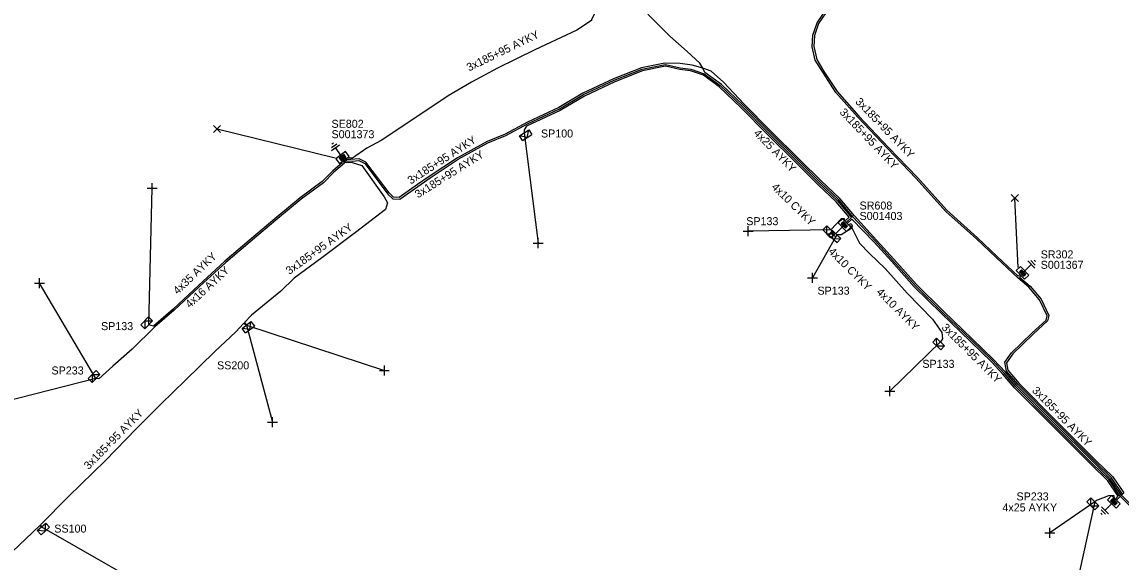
# Model space of a CAD drawing. Extents: x -763093 to -760976, y -1155572 to -1152009.
# Drawn here: x -761822.3 to -761685, y -1155229.2 to -1155161.8 of the extents above; entities that cross this region are included whole.
import ezdxf

# ---------------------------------------------------------------- set-up
doc = ezdxf.new("R2010")
doc.units = 0
for name, color, linetype in [('Vrstva 1', 7, 'Continuous'), ('Vrstva 14', 7, 'Continuous'), ('Vrstva 15', 7, 'Continuous'), ('Vrstva 28', 7, 'Continuous'), ('Vrstva 29', 7, 'Continuous'), ('Vrstva 30', 7, 'Continuous'), ('Vrstva 31', 7, 'Continuous'), ('Vrstva 33', 7, 'Continuous'), ('Vrstva 34', 7, 'Continuous'), ('Vrstva 5', 7, 'Continuous'), ('Vrstva 59', 7, 'Continuous'), ('Vrstva 6', 7, 'Continuous'), ('Vrstva 8', 7, 'Continuous'), ('Vrstva 9', 7, 'Continuous')]:
    doc.layers.add(name, color=color, linetype=linetype)

# ---------------------------------------------------------------- blocks, each defined once
blk = doc.blocks.new('NN800')
at = {"layer": 'Vrstva 1'}
for points in [[(-0.44, 0.44), (0.44, -0.44)], [(-0.44, -0.44), (0.44, 0.44)]]:
    blk.add_lwpolyline(points, dxfattribs=at)
blk = doc.blocks.new('NN620')
at = {"layer": 'Vrstva 8'}
for points in [[(0.75, 0), (-0.75, 0)], [(-0.75, 0), (-0.75, -0.75)], [(0.75, -0.75), (0.75, 0)], [(-0.75, -0.75), (0.75, -0.75)], [(0.37, -0.18), (-0.38, -0.18)], [(-0.38, -0.18), (-0.38, -0.56)], [(-0.38, -0.56), (0.37, -0.56)], [(0.32, -0.23), (-0.33, -0.23)], [(-0.33, -0.23), (-0.33, -0.51)], [(-0.33, -0.51), (0.32, -0.51)], [(0.27, -0.27), (-0.28, -0.27)], [(-0.28, -0.27), (-0.28, -0.46)], [(-0.28, -0.46), (0.27, -0.46)], [(0.23, -0.32), (-0.23, -0.32)], [(-0.23, -0.32), (-0.23, -0.42)], [(-0.23, -0.42), (0.23, -0.42)], [(-0.19, -0.37), (0.19, -0.37)], [(0.23, -0.42), (0.23, -0.32)], [(0.27, -0.46), (0.27, -0.27)], [(0.32, -0.51), (0.32, -0.23)], [(0.37, -0.56), (0.37, -0.18)]]:
    blk.add_lwpolyline(points, dxfattribs=at)
blk = doc.blocks.new('NN630')
at = {"layer": 'Vrstva 9'}
for points in [[(0, -0.7), (-0.7, 0)], [(-0.7, -0.7), (-0.7, 0), (0.7, 0), (0.7, -0.7)], [(-0.7, -0.7), (0.7, -0.7)], [(0, -0.7), (0.7, 0)]]:
    blk.add_lwpolyline(points, dxfattribs=at)
blk = doc.blocks.new('NN810')
at = {"layer": 'Vrstva 14'}
for points in [[(0, -0.64), (0, -1.89)], [(0.63, -1.89), (-0.62, -1.89)], [(0.39, -2.2), (-0.4, -2.2)], [(0, -2.52), (-0.12, -2.52)], [(0.14, -2.52), (0, -2.52)]]:
    blk.add_lwpolyline(points, dxfattribs=at)

msp = doc.modelspace()

# ---------------------------------------------------------------- linework, layer by layer
at = {"layer": 'Vrstva 5'}
for points in [[(-761768.03, -1155139.21), (-761767.63, -1155138.81), (-761763.94, -1155142.24), (-761760.67, -1155145.05), (-761755.98, -1155149.22), (-761752.03, -1155152.82), (-761750.22, -1155154.22), (-761749.45, -1155155.24), (-761749.26, -1155156.63), (-761749.38, -1155158.36), (-761750.51, -1155160.19), (-761751.15, -1155161.49), (-761751.15, -1155161.57), (-761752.97, -1155162.79), (-761758.24, -1155165.24), (-761762.88, -1155167.52), (-761766.15, -1155169.29), (-761769.04, -1155171), (-761773.34, -1155173.85), (-761777.41, -1155176.55), (-761779.2, -1155177.51), (-761780.99, -1155178.76), (-761781.49, -1155178.78), (-761781.54, -1155178.72)], [(-761709.12, -1155156.66), (-761709.35, -1155156.53), (-761710.03, -1155154.82), (-761711.31, -1155155.21), (-761713.6, -1155156.32), (-761716.64, -1155157.57), (-761720.05, -1155159.03), (-761721.41, -1155159.94), (-761722.77, -1155161.96), (-761723.3, -1155163.46), (-761723.36, -1155164.83), (-761723.01, -1155166.44), (-761722.1, -1155167.94), (-761720.45, -1155170.46), (-761717.73, -1155173.51), (-761714.02, -1155177.43), (-761710.43, -1155181.17), (-761706.73, -1155185.28), (-761702.92, -1155188.71), (-761700.45, -1155191.04), (-761697.82, -1155193.5), (-761697.67, -1155193.34)], [(-761684.79, -1155220.72), (-761686.17, -1155218.7), (-761688.25, -1155216.66), (-761693.33, -1155211.59), (-761697.85, -1155207.03), (-761699.28, -1155205.38), (-761699.52, -1155204.26), (-761698.68, -1155203.09), (-761696.09, -1155200.6), (-761694.34, -1155198.99), (-761694.22, -1155198.45), (-761695.16, -1155196.47), (-761696.48, -1155194.88), (-761697.89, -1155193.71), (-761700.59, -1155191.18), (-761703.06, -1155188.85), (-761706.87, -1155185.42), (-761710.57, -1155181.31), (-761714.16, -1155177.57), (-761717.87, -1155173.65), (-761720.61, -1155170.58), (-761722.26, -1155168.04), (-761723.19, -1155166.52), (-761723.56, -1155164.85), (-761723.5, -1155163.42), (-761722.95, -1155161.86), (-761721.55, -1155159.8)], [(-761682.4, -1155223.69), (-761685.16, -1155220.89), (-761686.47, -1155218.96), (-761688.53, -1155216.94), (-761693.61, -1155211.87), (-761698.15, -1155207.31), (-761699.58, -1155205.64), (-761701.04, -1155204.05), (-761703.66, -1155201.52), (-761707.29, -1155198.03), (-761710.67, -1155194.71), (-761713.53, -1155191.5), (-761715.68, -1155189.14), (-761718.45, -1155186.12), (-761720.27, -1155183.95), (-761722.58, -1155181.76), (-761725.26, -1155179.11), (-761728.92, -1155175.48), (-761732.19, -1155172.16), (-761734.92, -1155169.55), (-761736.97, -1155168.07), (-761737.24, -1155167.51), (-761737.61, -1155166.9), (-761739.19, -1155165.46), (-761741.37, -1155163.52), (-761744.1, -1155160.8)], [(-761781.87, -1155178.97), (-761781.77, -1155179.12), (-761781.07, -1155179.15), (-761780.22, -1155179.06), (-761779.47, -1155179.44), (-761776.59, -1155183.25), (-761775.98, -1155183.85), (-761775.1, -1155183.88), (-761771.32, -1155181.22), (-761767.8, -1155178.91), (-761764.12, -1155176.85), (-761761.87, -1155175.94), (-761759.04, -1155174.46), (-761755.15, -1155172.63), (-761752.13, -1155170.83), (-761748.33, -1155169.04), (-761744.83, -1155167.67), (-761741.92, -1155167.08), (-761740.08, -1155167.5), (-761738.72, -1155167.66), (-761737.06, -1155168.24), (-761735.05, -1155169.71), (-761732.33, -1155172.3), (-761729.06, -1155175.62), (-761725.4, -1155179.25), (-761722.72, -1155181.9), (-761720.41, -1155184.09), (-761718.67, -1155186.17), (-761719.29, -1155186.75)], [(-761682.26, -1155223.55), (-761684.99, -1155220.78), (-761686.32, -1155218.83), (-761688.39, -1155216.8), (-761693.47, -1155211.73), (-761698, -1155207.17), (-761699.43, -1155205.51), (-761700.9, -1155203.9), (-761703.52, -1155201.38), (-761707.15, -1155197.89), (-761710.53, -1155194.57), (-761713.38, -1155191.37), (-761715.53, -1155189), (-761718.3, -1155185.99), (-761720.12, -1155183.81), (-761722.44, -1155181.61), (-761725.12, -1155178.97), (-761728.78, -1155175.34), (-761732.05, -1155172.02), (-761734.66, -1155169.27), (-761736.18, -1155167.9), (-761737.24, -1155167.51), (-761738.56, -1155167.16), (-761740.06, -1155166.96), (-761741.99, -1155166.89), (-761744.89, -1155167.48), (-761748.41, -1155168.86), (-761752.22, -1155170.65), (-761755.24, -1155172.45), (-761759.13, -1155174.28), (-761761.95, -1155175.76), (-761764.2, -1155176.67), (-761767.9, -1155178.73), (-761771.44, -1155181.06), (-761772.89, -1155182.08), (-761775.16, -1155183.68), (-761775.9, -1155183.65), (-761776.43, -1155183.11), (-761779.33, -1155179.28), (-761780.18, -1155178.86), (-761781.2, -1155178.94), (-761781.62, -1155178.96), (-761781.71, -1155178.85)], [(-761719.43, -1155186.61), (-761718.94, -1155186.15), (-761720.56, -1155184.23), (-761722.81, -1155182.09), (-761725.54, -1155179.39), (-761729.2, -1155175.76), (-761732.47, -1155172.44), (-761735.18, -1155169.87), (-761737.16, -1155168.42), (-761738.76, -1155167.86), (-761740.12, -1155167.7), (-761741.92, -1155167.29), (-761744.77, -1155167.86), (-761748.25, -1155169.22), (-761752.04, -1155171.01), (-761755.06, -1155172.81), (-761759.27, -1155174.79), (-761759.58, -1155175.23), (-761759.56, -1155175.61)], [(-761782.02, -1155179.09), (-761781.88, -1155179.28), (-761781.07, -1155179.33), (-761779.86, -1155179.69), (-761777.04, -1155183.59), (-761776.65, -1155184.36), (-761776.89, -1155185.19), (-761780.62, -1155188.06), (-761784.83, -1155191.21), (-761788.3, -1155193.78), (-761789.95, -1155195.4), (-761793.64, -1155198.4), (-761794.49, -1155199.29), (-761794.25, -1155199.61), (-761794.63, -1155199.43), (-761795.59, -1155200.45), (-761798.21, -1155202.91), (-761801.89, -1155206.49), (-761804.97, -1155209.49), (-761808.05, -1155212.57), (-761811.89, -1155216.54), (-761816.49, -1155221.04), (-761820, -1155224.55), (-761819.87, -1155224.82), (-761820.14, -1155224.69), (-761821.83, -1155226.33), (-761824.34, -1155228.67)], [(-761782.18, -1155179.18), (-761782.02, -1155179.4), (-761783.33, -1155180.5), (-761784.65, -1155181.86), (-761787.41, -1155183.88), (-761790.36, -1155186.31), (-761792.95, -1155188.51), (-761796.84, -1155191.8), (-761800.12, -1155194.81), (-761803.29, -1155197.76), (-761805.7, -1155199.85), (-761808.54, -1155202.64), (-761810.96, -1155204.76), (-761812.69, -1155206.33), (-761813.06, -1155206.29)], [(-761782.35, -1155179.3), (-761782.3, -1155179.37), (-761783.47, -1155180.36), (-761784.79, -1155181.7), (-761787.53, -1155183.72), (-761790.48, -1155186.15), (-761793.07, -1155188.35), (-761796.98, -1155191.64), (-761800.26, -1155194.67), (-761803.43, -1155197.62), (-761805.88, -1155199.74), (-761806.47, -1155199.57)], [(-761719.54, -1155186.5), (-761719.53, -1155186.35), (-761719.95, -1155186.36), (-761721.25, -1155187.72)], [(-761685.65, -1155221.32), (-761685.33, -1155220.99), (-761686.63, -1155219.09), (-761688.67, -1155217.08), (-761693.75, -1155212.01), (-761698.29, -1155207.44), (-761699.73, -1155205.77), (-761701.18, -1155204.2), (-761703.8, -1155201.66), (-761707.43, -1155198.17), (-761710.81, -1155194.85), (-761713.68, -1155191.63), (-761715.83, -1155189.28), (-761718.61, -1155186.39), (-761719.15, -1155186.89)], [(-761718.88, -1155187.18), (-761718.71, -1155187.27), (-761718.75, -1155187.6), (-761719.94, -1155188.33), (-761720.51, -1155188.33)], [(-761719.01, -1155187.04), (-761718.71, -1155186.95), (-761718.56, -1155187.18), (-761718.6, -1155187.49), (-761717.65, -1155189.4), (-761716.4, -1155190.69), (-761714.44, -1155192.55), (-761711.7, -1155195.64), (-761708.52, -1155198.9), (-761707.39, -1155200.54), (-761707.29, -1155201.34), (-761707.52, -1155201.73)], [(-761697.53, -1155193.48), (-761697.67, -1155193.63), (-761696.34, -1155194.74), (-761694.98, -1155196.37), (-761694.02, -1155198.43), (-761694.16, -1155199.09), (-761695.95, -1155200.74), (-761698.52, -1155203.23), (-761699.31, -1155204.34), (-761699.13, -1155205.25), (-761697.71, -1155206.9), (-761693.15, -1155211.49), (-761688.11, -1155216.52), (-761686.01, -1155218.57), (-761684.65, -1155220.57), (-761685.49, -1155221.45)], [(-761685.79, -1155221.19), (-761685.89, -1155220.91), (-761686.56, -1155220.93), (-761688.06, -1155221.51), (-761688.26, -1155221.7)]]:
    msp.add_lwpolyline(points, dxfattribs=at)
at = {"layer": 'Vrstva 59'}
for points in [[(-761783.19, -1155178.76), (-761797.94, -1155175.13)], [(-761759.56, -1155175.61), (-761757.81, -1155189.38)], [(-761806.47, -1155199.57), (-761806.06, -1155182.5)], [(-761697.83, -1155192.41), (-761698.25, -1155183.75)], [(-761721.25, -1155187.72), (-761731.56, -1155187.88)], [(-761720.51, -1155188.33), (-761723.53, -1155193.7)], [(-761813.06, -1155206.29), (-761820.13, -1155194.38)], [(-761794.25, -1155199.61), (-761791, -1155211.75)], [(-761794.25, -1155199.61), (-761777.03, -1155205.3)], [(-761707.52, -1155201.73), (-761713.86, -1155207.89)], [(-761813.06, -1155206.29), (-761826.64, -1155209.74)], [(-761688.26, -1155221.7), (-761693.88, -1155225.57)], [(-761688.26, -1155221.7), (-761690.19, -1155230.38)], [(-761819.87, -1155224.82), (-761802.69, -1155234.63)]]:
    msp.add_lwpolyline(points, dxfattribs=at)

# ---------------------------------------------------------------- block references
at = {"layer": 'Vrstva 15'}
for p, rotation in [((-761782.04, -1155179), -144.76414720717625), ((-761719.27, -1155186.87), -45.760738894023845), ((-761697.55, -1155193.36), 134.0906194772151), ((-761685.62, -1155221.43), -45.497702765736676)]:
    msp.add_blockref('NN810', p, dxfattribs=dict(at, rotation=rotation))
at = {"layer": 'Vrstva 28'}
for p, rotation in [((-761782.04, -1155179), -143.65742223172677), ((-761719.27, -1155186.87), -45.676130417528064), ((-761697.55, -1155193.36), 134.0906193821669), ((-761685.62, -1155221.43), -43.6581903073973)]:
    msp.add_blockref('NN620', p, dxfattribs=dict(at, rotation=rotation))
at = {"layer": 'Vrstva 31'}
for p, rotation in [((-761759.56, -1155175.61), 31.847191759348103), ((-761721.25, -1155187.72), -45.69027787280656), ((-761720.51, -1155188.33), -42.348757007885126), ((-761806.47, -1155199.57), -134.4073480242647), ((-761794.25, -1155199.61), 37.583254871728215), ((-761707.52, -1155201.73), -44.60685336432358), ((-761813.06, -1155206.29), -135.2432918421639), ((-761688.26, -1155221.7), -45.653536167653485), ((-761819.87, -1155224.82), 41.77771612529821)]:
    msp.add_blockref('NN630', p, dxfattribs=dict(at, rotation=rotation))
at = {"layer": 'Vrstva 34'}
for p in [(-761797.94, -1155175.13), (-761698.25, -1155183.75)]:
    msp.add_blockref('NN800', p, dxfattribs=at)
for p, rotation in [((-761806.06, -1155182.5), 45), ((-761731.56, -1155187.88), 45), ((-761757.81, -1155189.38), 45), ((-761723.53, -1155193.7), 45), ((-761820.13, -1155194.38), 45), ((-761777.03, -1155205.3), 45.00000009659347), ((-761713.86, -1155207.89), 45), ((-761791, -1155211.75), 45), ((-761693.88, -1155225.57), 45)]:
    msp.add_blockref('NN800', p, dxfattribs=dict(at, rotation=rotation))

# ---------------------------------------------------------------- texts
at = {"layer": 'Vrstva 29'}
for s, p in [('S001373', (-761783.63, -1155176.28)), ('S001403', (-761717.65, -1155186.49)), ('S001367', (-761695.02, -1155192.59))]:
    msp.add_text(s, height=1, dxfattribs=at).set_placement(p)
at = {"layer": 'Vrstva 30'}
for s, p in [('SE802', (-761783.63, -1155174.98)), ('SR608', (-761717.65, -1155185.19)), ('SR302', (-761695.02, -1155191.29))]:
    msp.add_text(s, height=1, dxfattribs=at).set_placement(p)
at = {"layer": 'Vrstva 33'}
for s, p in [('SP100', (-761757.46, -1155176.19)), ('SP133', (-761731.81, -1155187.14)), ('SP133', (-761722.91, -1155195.82)), ('SP133', (-761812.43, -1155200.25)), ('SS200', (-761797.93, -1155205.15)), ('SP133', (-761709.8, -1155204.96)), ('SP233', (-761818.62, -1155205.79)), ('SP233', (-761698.04, -1155221.52)), ('SS100', (-761818.27, -1155225.54))]:
    msp.add_text(s, height=1, dxfattribs=at).set_placement(p)
at = {"layer": 'Vrstva 6'}
for s, rotation, p in [('3x185+95 AYKY', 25.899, (-761766.45, -1155167.96)), ('3x185+95 AYKY', 314.075, (-761718.25, -1155171.8)), ('3x185+95 AYKY', 313.597, (-761720.22, -1155173.1)), ('4x25 AYKY', 314.239, (-761730.95, -1155175.73)), ('3x185+95 AYKY', 32.856, (-761773.73, -1155182.08)), ('3x185+95 AYKY', 32.111, (-761772.83, -1155183.81)), ('4x10 CYKY', 315.689, (-761728.73, -1155182.47)), ('3x185+95 AYKY', 35.77, (-761788.9, -1155193.37)), ('4x35 AYKY', 43.42, (-761802.86, -1155195.86)), ('4x10 CYKY', 315, (-761721.63, -1155190.52)), ('4x16 AYKY', 42.671, (-761801.34, -1155197.56)), ('4x10 AYKY', 314.989, (-761715.62, -1155195.58)), ('3x185+95 AYKY', 315.022, (-761707.48, -1155200.01)), ('3x185+95 AYKY', 314.789, (-761696.18, -1155207.88)), ('3x185+95 AYKY', 45.381, (-761813.98, -1155217.73)), ('4x25 AYKY', 0.102, (-761699.8, -1155222.9))]:
    msp.add_text(s, height=1, rotation=rotation, dxfattribs=at).set_placement(p)

doc.saveas('drawing.dxf')
